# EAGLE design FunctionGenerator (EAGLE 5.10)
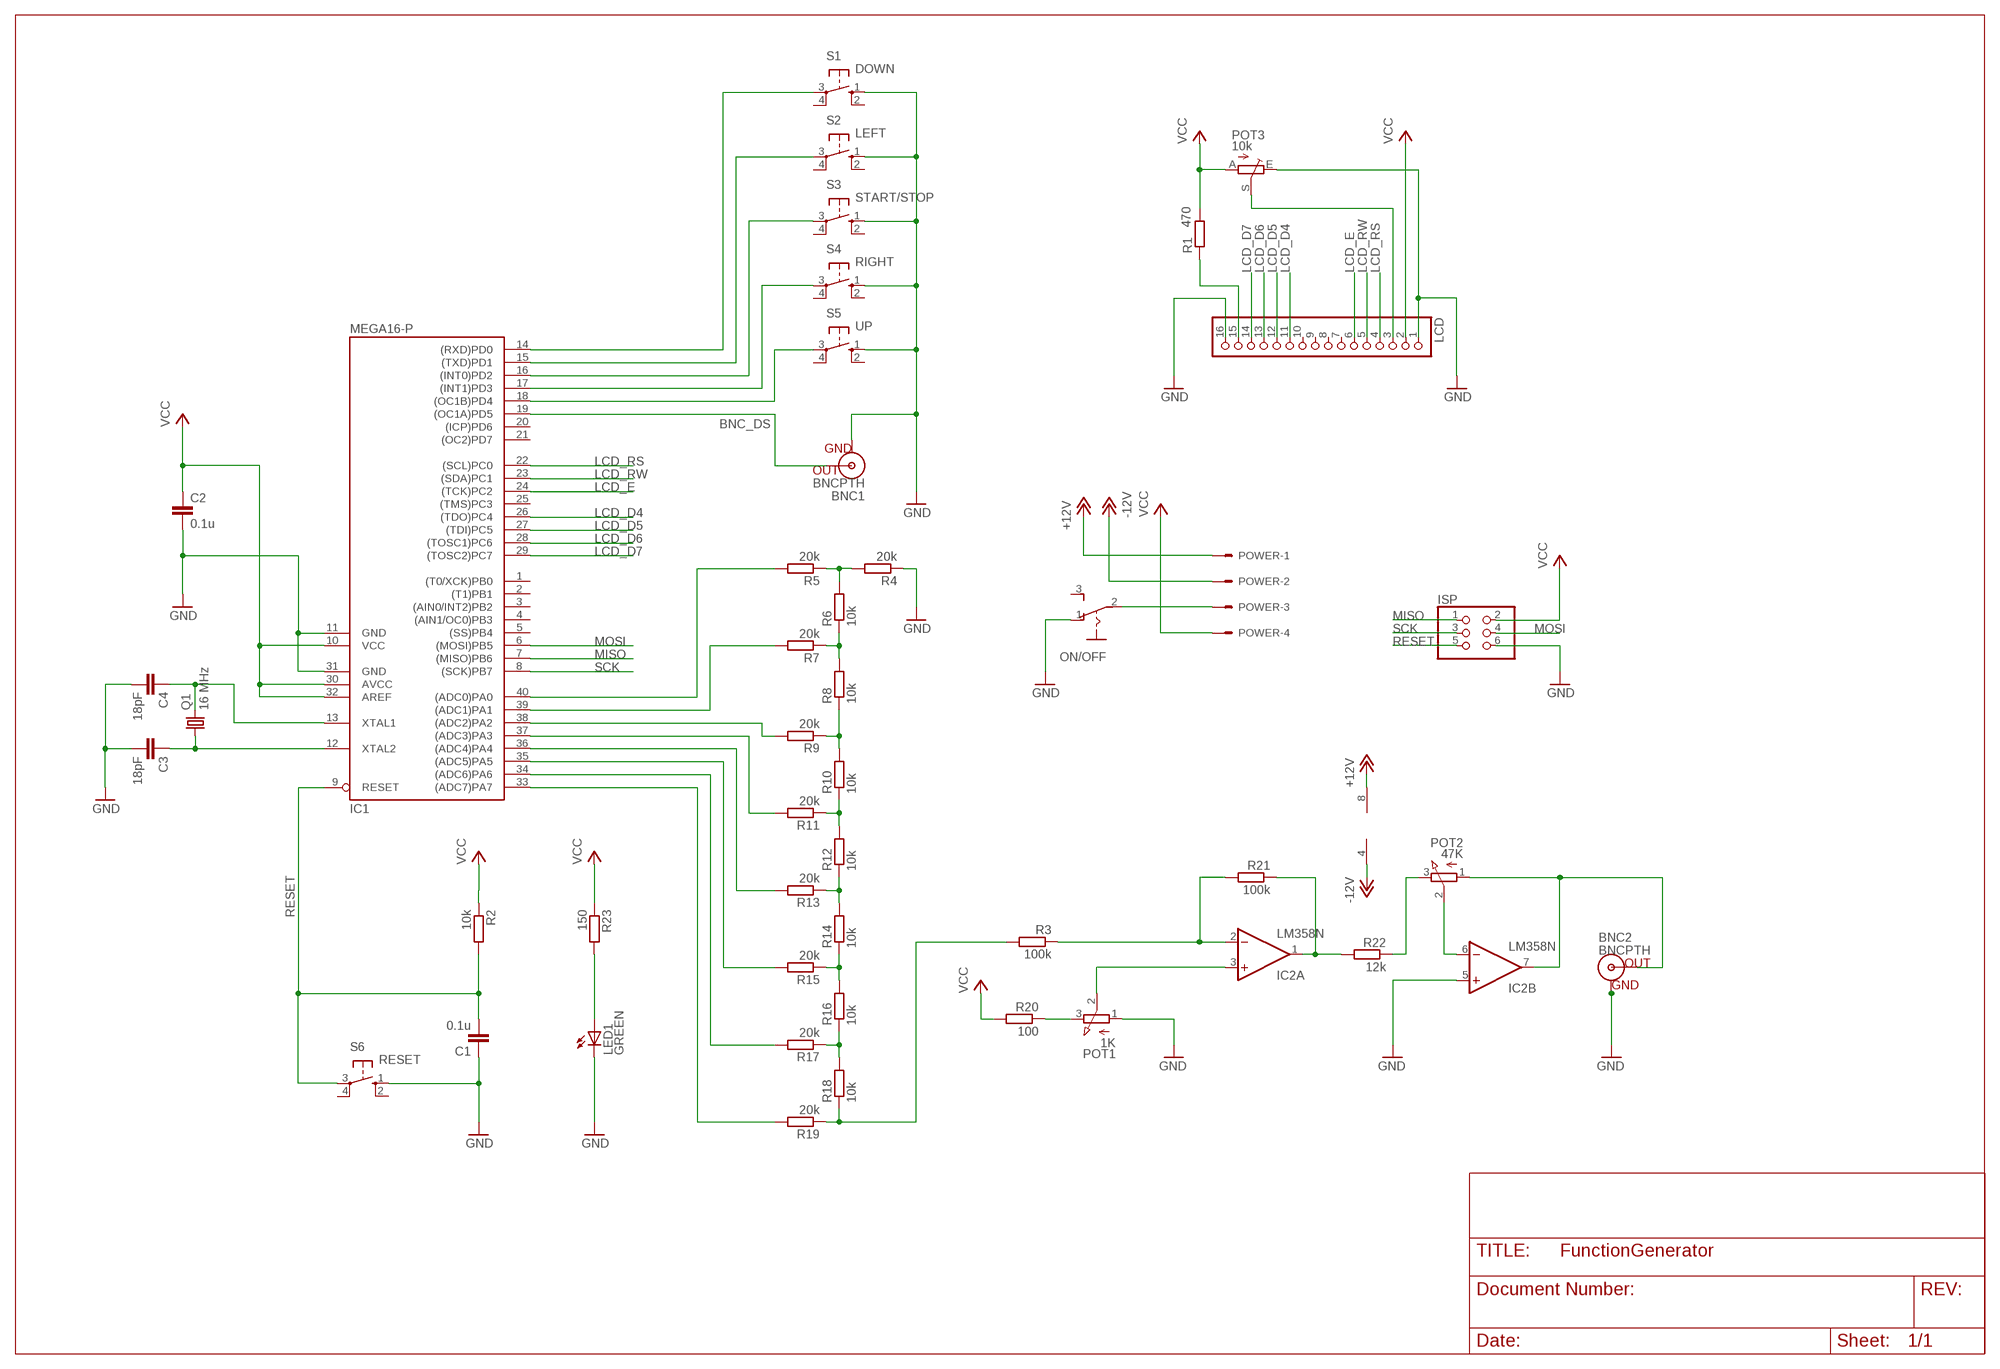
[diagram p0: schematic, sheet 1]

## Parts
BNC1  BNCPTH  [BNC]
BNC2  BNCPTH  [BNC]
C1  0.1u  C-EU050-030X075  [C050-030X075]
C2  0.1u  C-EU050-030X075  [C050-030X075]
C3  18pF  C-EU025-025X050  [C025-025X050]
C4  18pF  C-EU025-025X050  [C025-025X050]
IC1  MEGA16-P  [DIL40]
IC2  LM358N  [DIL08]
ISP  PINHD-2X3  [2X03]
LCD  PINHD-1X16  [1X16]
LED1  GREEN  LED3MM  [LED3MM]
ON/OFF  255SB  [255SB]
POT1  1K  3RP/1610N  [3RP/1610N]
POT2  47K  3RP/1610N  [3RP/1610N]
POT3  10k  TRIM_EU-LI10  [LI10]
POWER  22-27-2041-04  [6410-04]
Q1  16 MHz  CRYSTALHC49UV  [HC49U-V]
R1  470  R-EU_0309/12  [0309/12]
R2  10k  R-EU_0207/10  [0207/10]
R3  100k  R-EU_0207/10  [0207/10]
R4  20k  R-EU_0207/10  [0207/10]
R5  20k  R-EU_0207/10  [0207/10]
R6  10k  R-EU_0207/10  [0207/10]
R7  20k  R-EU_0207/10  [0207/10]
R8  10k  R-EU_0207/10  [0207/10]
R9  20k  R-EU_0207/10  [0207/10]
R10  10k  R-EU_0207/10  [0207/10]
R11  20k  R-EU_0207/10  [0207/10]
R12  10k  R-EU_0207/10  [0207/10]
R13  20k  R-EU_0207/10  [0207/10]
R14  10k  R-EU_0207/10  [0207/10]
R15  20k  R-EU_0207/10  [0207/10]
R16  10k  R-EU_0207/10  [0207/10]
R17  20k  R-EU_0207/10  [0207/10]
R18  10k  R-EU_0207/10  [0207/10]
R19  20k  R-EU_0207/10  [0207/10]
R20  100  R-EU_0207/10  [0207/10]
R21  100k  R-EU_0207/10  [0207/10]
R22  12k  R-EU_0207/10  [0207/10]
R23  150  R-EU_0207/10  [0207/10]
S1  DOWN  10-XX  [B3F-10XX]
S2  LEFT  10-XX  [B3F-10XX]
S3  START/STOP  10-XX  [B3F-10XX]
S4  RIGHT  10-XX  [B3F-10XX]
S5  UP  10-XX  [B3F-10XX]
S6  RESET  10-XX  [B3F-10XX]

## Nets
+12V: IC2.8(P:V+) POWER.1
-12V: IC2.4(P:V-) POWER.2
BNC_DDS: BNC2.S(OUT) IC2.7(B:OUT) POT2.1(A)
BNC_DS: BNC1.S(OUT) IC1.19((OC1A)PD5)
DDS_OUT: R3.2 R18.1 R19.1
DOWN: IC1.14((RXD)PD0) S1.3(P)
GND: BNC1.GND BNC2.GND C1.1 C2.2 C3.2 C4.2 IC1.11(GND) IC1.31(GND) IC2.5(B:+IN) ISP.6 LCD.1 LCD.16 LED1.K(C) ON/OFF.1(O) POT1.1(A) POT3.E R4.1 S1.1(S) S2.1(S) S3.1(S) S4.1(S) S5.1(S) S6.1(S)
LCD_D4: IC1.26((TDO)PC4) LCD.11
LCD_D5: IC1.27((TDI)PC5) LCD.12
LCD_D6: IC1.28((TOSC1)PC6) LCD.13
LCD_D7: IC1.29((TOSC2)PC7) LCD.14
LCD_E: IC1.24((TCK)PC2) LCD.6
LCD_RS: IC1.22((SCL)PC0) LCD.4
LCD_RW: IC1.23((SDA)PC1) LCD.5
LEFT: IC1.15((TXD)PD1) S2.3(P)
MISO: IC1.7((MISO)PB6) ISP.1
MOSI: IC1.6((MOSI)PB5) ISP.4
N$1: IC1.40((ADC0)PA0) R5.2
N$2: LCD.3 POT3.S
N$3: IC2.2(A:-IN) R3.1 R21.2
N$4: LED1.A R23.2
N$5: LCD.15 R1.1
N$6: IC1.39((ADC1)PA1) R7.2
N$7: IC1.33((ADC7)PA7) R19.2
N$8: IC1.34((ADC6)PA6) R17.2
N$9: IC1.35((ADC5)PA5) R15.2
N$10: IC1.36((ADC4)PA4) R13.2
N$11: IC1.37((ADC3)PA3) R11.2
N$12: IC1.38((ADC2)PA2) R9.2
N$13: POT2.3(E) R22.1
N$14: IC2.3(A:+IN) POT1.2(S)
N$15: R4.2 R5.1 R6.2
N$16: IC2.1(A:OUT) R21.1 R22.2
N$17: POT1.3(E) R20.1
N$18: R6.1 R7.1 R8.2
N$19: ON/OFF.2(P) POWER.3
N$20: R8.1 R9.1 R10.2
N$21: R10.1 R11.1 R12.2
N$22: R12.1 R13.1 R14.2
N$23: R14.1 R15.1 R16.2
N$24: R16.1 R17.1 R18.2
N$25: IC2.6(B:-IN) POT2.2(S)
RESET: C1.2 IC1.9(RESET) ISP.5 R2.2 S6.3(P)
RIGHT: IC1.17((INT1)PD3) S4.3(P)
SCK: IC1.8((SCK)PB7) ISP.3
START/STOP: IC1.16((INT0)PD2) S3.3(P)
UP: IC1.18((OC1B)PD4) S5.3(P)
VCC: C2.1 IC1.10(VCC) IC1.30(AVCC) IC1.32(AREF) ISP.2 LCD.2 POT3.A POWER.4 R1.2 R2.1 R20.2 R23.1
XTAL1: C4.1 IC1.13(XTAL1) Q1.2
XTAL2: C3.1 IC1.12(XTAL2) Q1.1
Unconnected: IC1.1((T0/XCK)PB0) IC1.2((T1)PB1) IC1.3((AIN0/INT2)PB2) IC1.4((AIN1/OC0)PB3) IC1.5((SS)PB4) IC1.20((ICP)PD6) IC1.21((OC2)PD7) IC1.25((TMS)PC3) LCD.7 LCD.8 LCD.9 LCD.10 ON/OFF.3(S) S1.2(S1) S1.4(P1) S2.2(S1) S2.4(P1) S3.2(S1) S3.4(P1) S4.2(S1) S4.4(P1) S5.2(S1) S5.4(P1) S6.2(S1) S6.4(P1)

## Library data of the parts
BNC1 BNC2 = SparkFun:BNC: BNC Connector, Mouser Part# 5227161
C1-C4 = rcl:C-EU: CAPACITOR, European symbol
IC1 = atmel:MEGA16-P: MICROCONTROLLER 16 Kbytes FLASH 1 kbytes SRAM 512 bytes EEPROM USART 8-channel 10 bit ADC Source: avr.lbr
IC2 = linear:LM358: OP AMP also LM158; LM258; LM2904 Source: http://cache.national.com/ds/LM/LM158.pdf
ISP = pinhead:PINHD-2X3: PIN HEADER
LCD = pinhead:PINHD-1X16: PIN HEADER
LED1 = led:LED: LED
ON/OFF = switch:255SB: SLIDING SWITCH Distributor Buerklin, 11G810
POT1 POT2 = pot:3RP/1610N: 16mm Potentiometer one level Source: http://www.alphapotentiometers.net/html/16mm_pot_2.html
POT3 = pot:TRIM_EU-: POTENTIOMETER
POWER = con-molex:22-?-04: CONNECTOR wire to board 2.54 mm (.1 inch) pitch header
Q1 = SparkFun:CRYSTAL: Crystals
R1-R23 = rcl:R-EU_: RESISTOR, European symbol
S1-S6 = switch-omron:10-XX: OMRON SWITCH

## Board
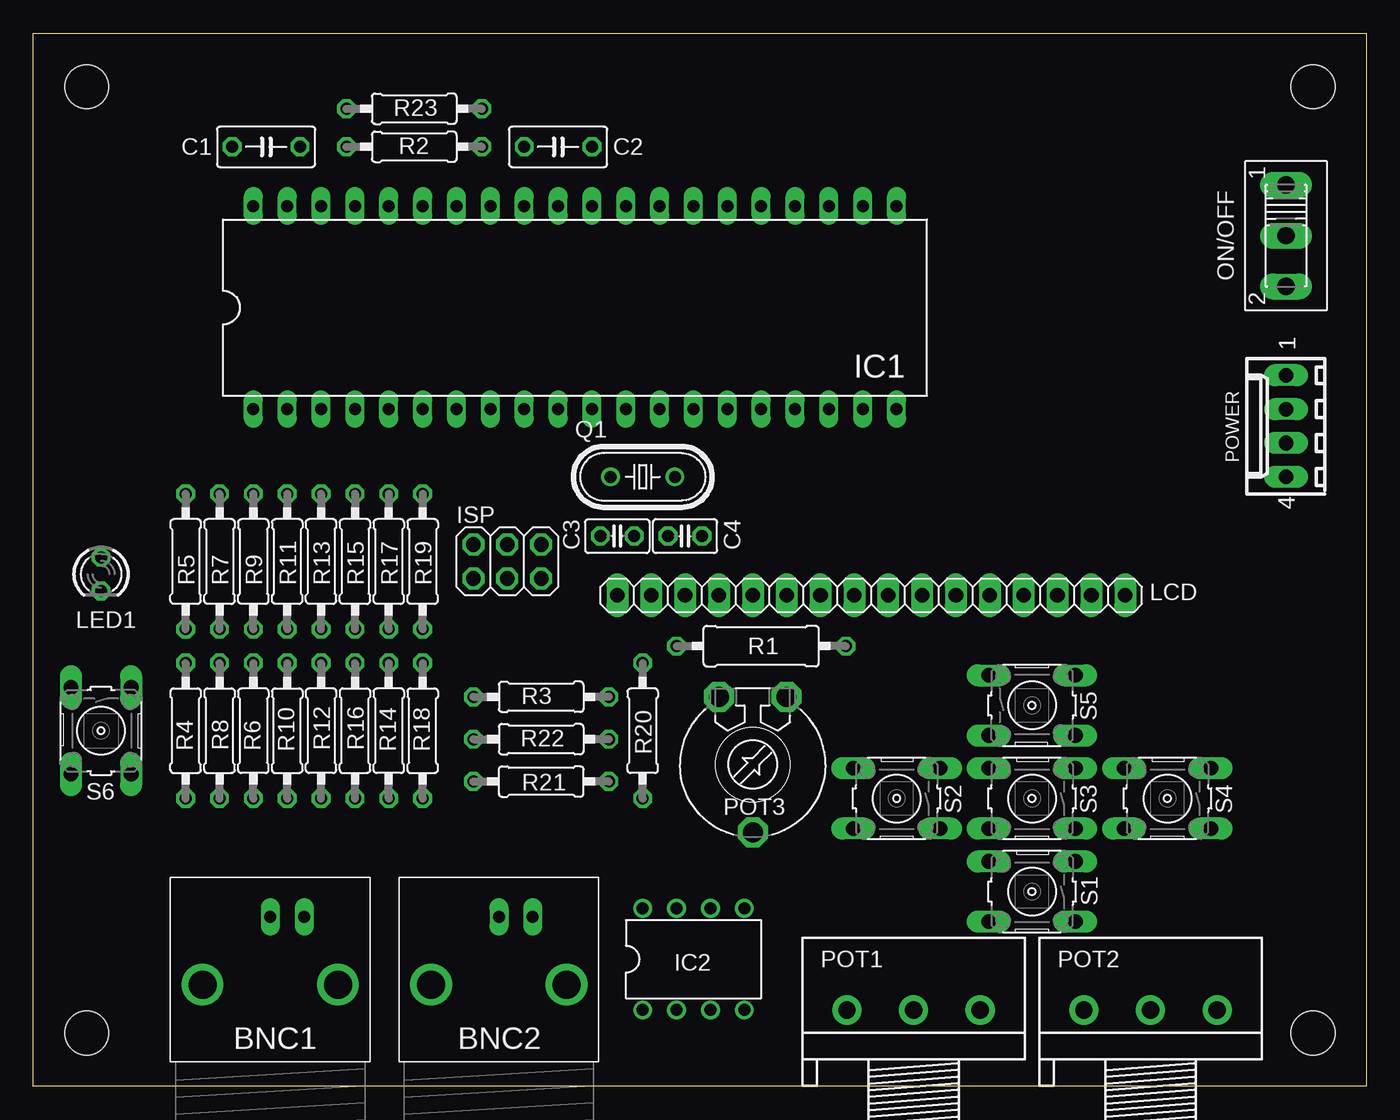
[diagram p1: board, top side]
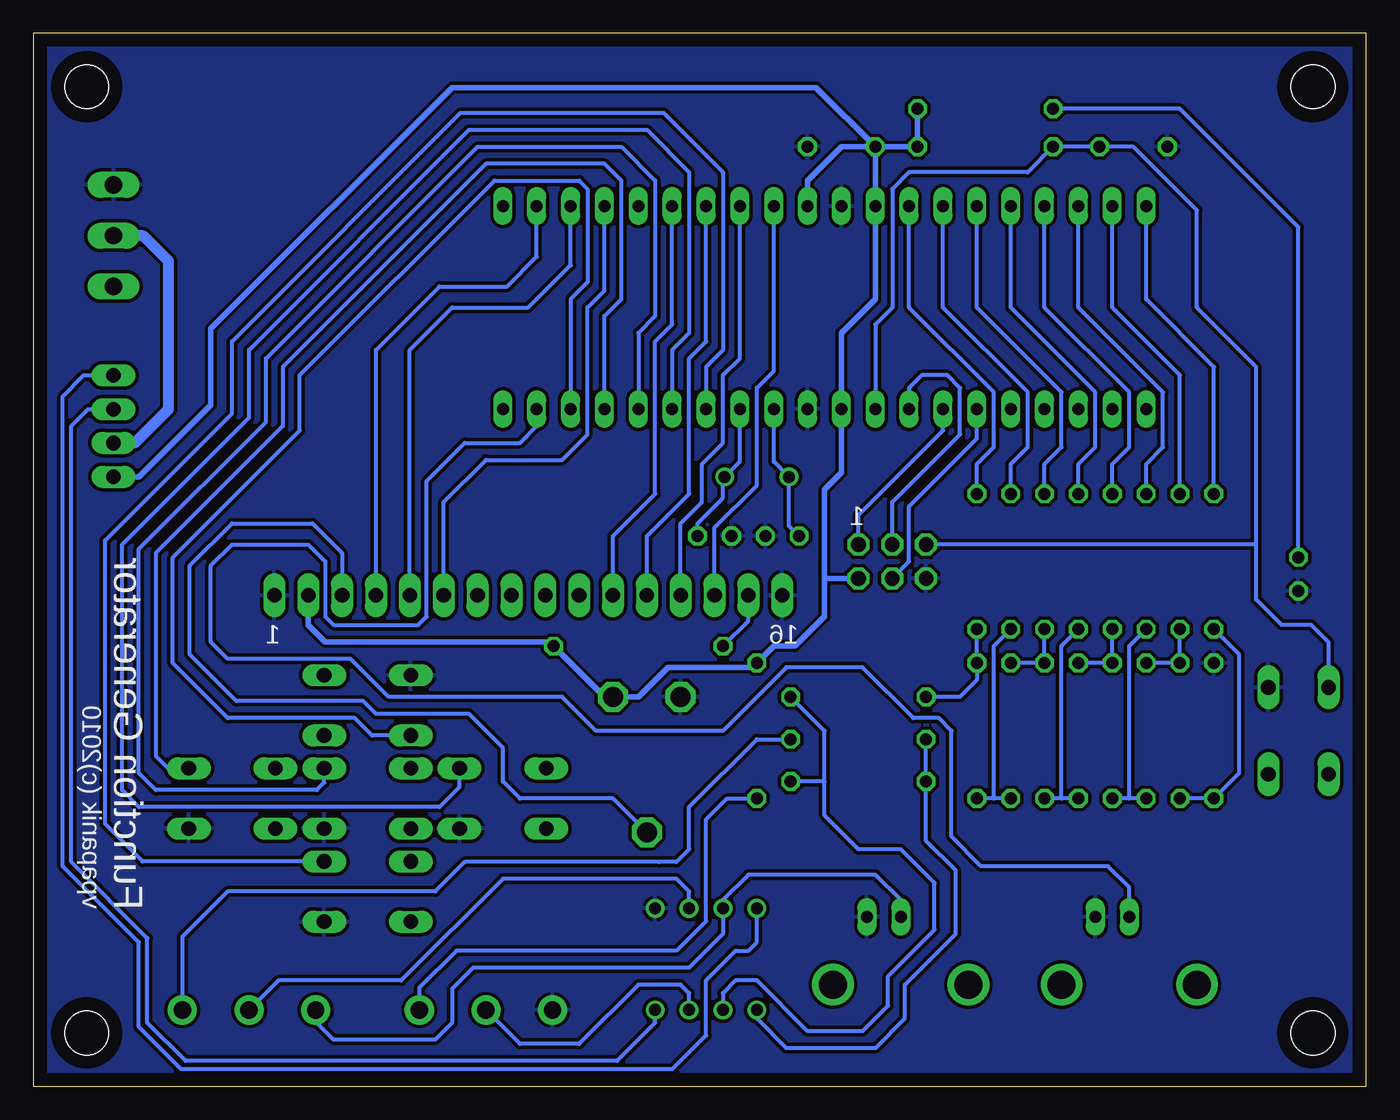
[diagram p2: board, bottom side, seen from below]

Size 100 x 79 mm. Coordinates in mm from the lower left corner, seen from the top.
Outline: 0,79 100,79 100,0 0,0 0,79
Copper layers (1*16): Top 0.035mm / dielectric 1.5mm / Bottom 0.035mm
Design rules "OLIMEX_10mils": minimum track width 10mil, minimum drill 24mil, track to track 10mil, track to pad 10mil, pad to pad 10mil, via to via 10mil, smd to smd 10mil, copper to edge 40mil, drill to drill 10mil, minimum pad ring 10mil, minimum via ring 8mil, stop-mask expansion 0mil, vias tented up to drill 0mil, thermal gap 10mil
Holes 3.3 mm at 4,75 96,75 96,4 4,4

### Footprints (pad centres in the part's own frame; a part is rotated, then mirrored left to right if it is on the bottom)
BNC = drill 2.1 round: 3 -5.08,5.08; 4 5.08,5.08 | drill 0.9 long: GND -2.54,0; S 0,0
C050-030X075 = drill 0.9 octagon: 1 -2.54,0; 2 2.54,0
C025-025X050 = drill 0.9 octagon: 1 -1.27,0; 2 1.27,0
DIL40 = drill 0.9 long: 1 -24.13,-7.62; 2 -21.59,-7.62; 3 -19.05,-7.62; 4 -16.51,-7.62; 5 -13.97,-7.62; 6 -11.43,-7.62; 7 -8.89,-7.62; 8 -6.35,-7.62; 9 -3.81,-7.62; 10 -1.27,-7.62; 11 1.27,-7.62; 12 3.81,-7.62; 13 6.35,-7.62; 14 8.89,-7.62; 15 11.43,-7.62; 16 13.97,-7.62; 17 16.51,-7.62; 18 19.05,-7.62; 19 21.59,-7.62; 20 24.13,-7.62; 21 24.13,7.62; 22 21.59,7.62; 23 19.05,7.62; 24 16.51,7.62; 25 13.97,7.62; 26 11.43,7.62; 27 8.89,7.62; 28 6.35,7.62; 29 3.81,7.62; 30 1.27,7.62; 31 -1.27,7.62; 32 -3.81,7.62; 33 -6.35,7.62; 34 -8.89,7.62; 35 -11.43,7.62; 36 -13.97,7.62; 37 -16.51,7.62; 38 -19.05,7.62; 39 -21.59,7.62; 40 -24.13,7.62
DIL08 = drill 0.9 pad 1.27 round: 1 -3.81,-3.81; 2 -1.27,-3.81; 3 1.27,-3.81; 4 3.81,-3.81; 5 3.81,3.81; 6 1.27,3.81; 7 -1.27,3.81; 8 -3.81,3.81
2X03 = drill 1.1 octagon: 1 -2.54,-1.27; 2 -2.54,1.27; 3 0,-1.27; 4 0,1.27; 5 2.54,-1.27; 6 2.54,1.27
1X16 = drill 1.1 long: 1 -19.05,0; 2 -16.51,0; 3 -13.97,0; 4 -11.43,0; 5 -8.89,0; 6 -6.35,0; 7 -3.81,0; 8 -1.27,0; 9 1.27,0; 10 3.81,0; 11 6.35,0; 12 8.89,0; 13 11.43,0; 14 13.97,0; 15 16.51,0; 16 19.05,0
LED3MM = drill 0.9 octagon: A -1.27,0; K 1.27,0
255SB = drill 1.3 long: 1 -3.81,0; 2 0,0; 3 3.81,0
3RP/1610N = drill 1.3 pad 2.184 round: 1 -5,0; 2 0,0; 3 5,0
LI10 = drill 1.5 octagon: A -2.54,-5.08; E 2.54,-5.08; S 0,5.08
6410-04 = drill 1.1 long: 1 3.81,0; 2 1.27,0; 3 -1.27,0; 4 -3.81,0
HC49U-V = drill 0.9 round: 1 -2.413,0; 2 2.413,0
0309/12 = drill 0.9 octagon: 1 -6.35,0; 2 6.35,0
0207/10 = drill 0.9 octagon: 1 -5.08,0; 2 5.08,0
B3F-10XX = drill 1.1 long: 1 -3.251,2.261; 2 3.251,2.261; 3 -3.251,-2.261; 4 3.251,-2.261

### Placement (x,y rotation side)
BNC1  17.78,12.7 180 top
BNC2  34.92,12.7 180 top
C1  17.46,70.48 0 top
C2  39.37,70.48 0 top
C3  43.81,41.27 0 top
C4  48.9,41.27 180 top
IC1  40.64,58.42 0 top
IC2  49.53,9.53 0 top
ISP  35.56,39.37 180 top
LCD  62.87,36.83 180 top
LED1  5.08,38.42 270 top
ON/OFF  93.98,63.82 270 top
POT1  66.04,5.71 0 top
POT2  83.82,5.71 0 top
POT3  53.98,24.13 180 top
POWER  93.98,49.53 90 top
Q1  45.72,45.72 0 top
R1  54.61,33.02 0 top
R2  28.57,70.48 180 top
R3  38.1,29.21 180 top
R4  11.43,26.67 270 top
R5  11.43,39.37 90 top
R6  13.97,26.67 270 top
R7  13.97,39.37 90 top
R8  16.51,26.67 90 top
R9  16.51,39.37 90 top
R10  19.05,26.67 270 top
R11  19.05,39.37 90 top
R12  21.59,26.67 90 top
R13  21.59,39.37 90 top
R14  24.13,26.67 270 top
R15  24.13,39.37 90 top
R16  26.67,26.67 90 top
R17  26.67,39.37 90 top
R18  29.21,26.67 270 top
R19  29.21,39.37 90 top
R20  45.72,26.67 90 top
R21  38.1,22.86 0 top
R22  38.1,26.04 180 top
R23  28.57,73.34 180 top
S1  74.93,14.61 180 top
S2  64.77,21.59 180 top
S3  74.93,21.59 180 top
S4  85.09,21.59 180 top
S5  74.93,28.57 0 top
S6  5.08,26.67 270 top

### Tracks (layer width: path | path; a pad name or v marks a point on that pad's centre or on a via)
+12V
  Bottom 0.305: IC2.8 45.72,10.79 46.35,10.16 47.31,10.16 49.53,7.94 49.53,3.81 52.07,1.27 88.58,1.27 88.9,1.27 92.08,4.45 92.08,10.79 97.79,16.51 97.79,51.75 96.2,53.34 POWER.1
-12V
  Bottom 0.305: IC2.4 53.34,4.76 56.2,1.91 88.58,1.91 91.44,4.76 91.44,11.11 97.16,16.83 97.16,49.53 95.89,50.8 POWER.2
BNC_DDS
  Bottom 0.305: BNC2.S 34.92,13.97 36.83,15.88 46.35,15.88 48.26,13.97 IC2.7 48.26,11.43 50.8,8.89 66.99,8.89 68.58,7.3 68.58,4.76 69.85,3.49 77.47,3.49 78.82,4.84 POT2.1
BNC_DS
  Bottom 0.305: BNC1.S 17.78,14.92 19.37,16.51 28.89,16.51 31.11,18.73 31.11,26.67 32.07,27.62 33.97,27.62 37.78,31.43 43.5,31.43 48.26,26.67 57.78,26.67 60.33,29.21 73.34,29.21 76.2,32.07 85.41,32.07 86.68,33.34 86.68,39.05 85.09,40.64 79.38,40.64 78.11,39.37 78.11,35.24 77.47,34.61 71.12,34.61 70.48,35.24 70.48,45.4 67.63,48.26 63.5,48.26 62.23,49.53 IC1.19
DDS_OUT
  Bottom 0.305: R19.1 R18.1 29.21,30.48 30.48,29.21 R3.2
DOWN
  Bottom 0.305: IC1.14 49.53,53.98 48.26,55.24 48.26,68.58 52.7,73.03 67.94,73.03 85.09,55.88 85.09,50.48 94.61,40.96 94.61,19.68 91.8,16.87 S1.3
GND
  pour Bottom (isolate 0.254): 0,0 100,0 100,79 0,79
LCD_D4
  Bottom 0.305: IC1.26 52.07,57.15 53.34,55.88 53.34,44.45 56.52,41.27 LCD.11
LCD_D5
  Bottom 0.305: IC1.27 49.53,55.88 50.8,54.61 50.8,44.45 53.98,41.27 LCD.12
LCD_D6
  Bottom 0.305: IC1.28 46.99,54.61 48.26,53.34 48.26,48.26 49.85,46.67 49.85,43.81 51.44,42.23 LCD.13
LCD_D7
  Bottom 0.305: IC1.29 44.45,53.66 45.72,52.39 45.72,45.09 48.9,41.91 LCD.14
LCD_E
  Bottom 0.305: IC1.24 57.15,59.69 58.42,58.42 58.42,48.9 60.33,46.99 66.04,46.99 69.22,43.81 LCD.6
LCD_RS
  Bottom 0.305: IC1.22 62.23,62.23 64.45,60.01 69.53,60.01 74.3,55.24 LCD.4
LCD_RW
  Bottom 0.305: IC1.23 59.69,61.59 62.87,58.42 68.58,58.42 71.75,55.24 LCD.5
LEFT
  Bottom 0.305: IC1.15 52.07,55.24 50.8,56.52 50.8,68.58 53.98,71.75 67.31,71.75 83.82,55.24 83.82,50.16 93.34,40.64 93.34,22.23 92.08,20.95 69.53,20.95 68.02,22.47 S2.3
MISO
  Bottom 0.305: IC1.7 31.75,49.21 38.1,42.86 ISP.1
MOSI
  Bottom 0.305: IC1.6 29.21,48.58 34.29,43.5 34.29,39.37 ISP.4
N$1
  Bottom 0.305: R5.2 11.43,53.98 16.51,59.05 IC1.40
N$2
  Bottom 0.305: POT3.S 56.52,21.59 63.5,21.59 64.77,22.86 64.77,25.4 67.31,27.94 74.3,27.94 75.25,28.89 84.77,28.89 88.27,32.38 88.27,39.05 85.09,42.23 79.06,42.23 76.83,40.01 LCD.3
N$3
  Bottom 0.305: R3.1 40.64,26.67 40.64,22.86 | 40.64,22.86 R21.2 | 40.64,22.86 40.64,20.32 38.1,17.78 34.92,17.78 32.38,15.24 32.38,11.75 35.88,8.26 35.88,6.03 37.78,4.13 41.91,4.13 45.72,7.94 47.31,7.94 48.26,6.99 IC2.2
N$4
  Bottom 0.305: R23.2 13.97,73.34 5.08,64.45 LED1.A
N$5
  Bottom 0.305: LCD.15 46.35,34.92 R1.1
N$6
  Bottom 0.305: R7.2 13.97,53.34 19.05,58.42 IC1.39
N$7
  Bottom 0.305: R19.2 29.21,46.67 27.94,47.94 27.94,52.07 34.29,58.42 IC1.33
N$8
  Bottom 0.305: R17.2 26.67,46.67 25.4,47.94 25.4,52.07 31.75,58.42 IC1.34
N$9
  Bottom 0.305: R15.2 24.13,46.67 22.86,47.94 22.86,52.07 29.21,58.42 IC1.35
N$10
  Bottom 0.305: R13.2 21.59,46.67 20.32,47.94 20.32,52.07 26.67,58.42 IC1.36
N$11
  Bottom 0.305: R11.2 19.05,46.67 17.78,47.94 17.78,52.07 24.13,58.42 IC1.37
N$12
  Bottom 0.305: R9.2 16.51,46.67 15.24,47.94 15.24,52.07 21.59,58.42 IC1.38
N$13
  Bottom 0.305: POT2.3 88.82,11.19 85.41,14.61 69.85,14.61 67.63,16.83 53.02,16.83 51.75,16.83 50.8,17.78 50.8,20.95 45.72,26.04 R22.1
N$14
  Bottom 0.305: IC2.3 50.8,6.99 51.44,7.62 54.61,7.62 59.05,3.17 63.5,3.17 POT1.2
N$15
  Bottom 0.305: R5.1 9.53,32.38 9.53,23.5 R4.2 R6.2
N$16
  Bottom 0.305: R22.2 R21.1 33.02,18.41 30.8,16.19 30.8,11.43 34.61,7.62 34.61,5.08 36.83,2.86 43.5,2.86 45.72,5.08 IC2.1
N$17
  Bottom 0.305: POT1.3 71.04,7.38 68.26,10.16 51.75,10.16 49.53,12.38 49.53,20 47.94,21.59 R20.1
N$18
  Bottom 0.305: R7.1 R6.1 R8.2
N$19
  Bottom 0.813: ON/OFF.2 91.76,63.82 89.85,61.91 89.85,50.8 92.39,48.26 POWER.3
N$20
  Bottom 0.305: R9.1 17.78,33.02 17.78,21.59 | R8.1 17.78,21.59 | 17.78,21.59 R10.2
N$21
  Bottom 0.305: R11.1 R10.1 R12.2
N$22
  Bottom 0.305: R13.1 22.86,33.02 22.86,21.59 | R12.1 22.86,21.59 | 22.86,21.59 R14.2
N$23
  Bottom 0.305: R15.1 R14.1 R16.2
N$24
  Bottom 0.305: R17.1 27.94,33.02 27.94,21.59 | R16.1 27.94,21.59 | 27.94,21.59 R18.2
N$25
  Bottom 0.305: IC2.6 50.8,14.61 51.75,15.56 64.77,15.56 72.39,7.94 81.6,7.94 POT2.2
RESET
  Bottom 0.305: 8.26,40.64 ISP.5 | 8.26,40.64 8.26,53.98 12.7,58.42 12.7,65.72 17.46,70.48 C1.2 R2.2 25.4,68.58 34.29,68.58 35.56,67.31 35.56,58.42 36.83,57.15 IC1.9 | S6.3 2.82,33.3 4.13,34.61 6.35,34.61 8.26,36.51 8.26,40.64
RIGHT
  Bottom 0.305: IC1.17 57.15,57.78 55.88,59.05 55.88,67.94 57.15,69.22 66.04,69.22 81.28,53.98 81.28,49.53 90.81,40.01 90.81,24.77 89.89,23.85 S4.3
SCK
  Bottom 0.305: ISP.3 35.56,43.81 30.48,48.9 30.48,52.39 31.43,53.34 33.34,53.34 34.29,52.39 IC1.8
START/STOP
  Bottom 0.305: IC1.16 54.61,56.52 53.34,57.78 53.34,67.94 55.88,70.48 66.67,70.48 82.55,54.61 82.55,49.85 92.08,40.32 92.08,23.5 90.81,22.23 78.74,22.23 78.18,22.78 S3.3
UP
  Bottom 0.305: IC1.18 59.69,59.05 58.42,60.33 58.42,67.31 59.05,67.94 65.41,67.94 80.01,53.34 80.01,49.21 89.53,39.69 89.53,31.75 85.41,27.62 75.88,27.62 74.57,26.31 S5.3
VCC
  Bottom 0.406: C2.1 IC1.32 36.83,59.05 39.37,56.52 IC1.10 39.37,46.04 40.64,44.77 40.64,38.1 | 40.64,38.1 ISP.2 | C2.1 41.27,74.93 68.58,74.93 86.68,56.83 86.68,51.12 92.08,45.72 POWER.4 | C2.1 R2.1 R23.1 | LCD.2 79.38,34.61 78.11,33.34 61.28,33.34 R1.2 57.15,29.21 POT3.A 54.61,29.21 52.39,31.43 46.04,31.43 R20.2 44.45,33.02 42.86,33.02 40.64,35.24 40.64,38.1 | IC1.30 41.91,67.94 39.37,70.48 C2.1
XTAL1
  Bottom 0.305: IC1.13 46.99,46.86 Q1.2 48.26,45.59 48.26,44.13 50.16,42.23 C4.1
XTAL2
  Bottom 0.305: IC1.12 44.45,46.86 Q1.1 43.31,42.04 C3.1

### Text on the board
bNames: 1 | Function Generator | 16 | 1 | vpapanik (c)2010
